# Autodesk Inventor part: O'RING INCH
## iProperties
SIZE: 0.139 in
I_D: 0.734 in
d1: SIZE
d0: I_D
Author: francis routh
Shininess: 20.0
PropertySet Name: _Private Model Information
Created: 2001-07
Part Number: O'RING INCH
Document SubType Name: Modeling
Designer: francis routh
Control State: 0
Master: False
Checked Out: False
PropertySet Name: Design Tracking Control
Density: 0.0
Volumn: 0.0
Area: 0.0
PropertySet Name: Model Information
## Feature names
1. Revolution1
